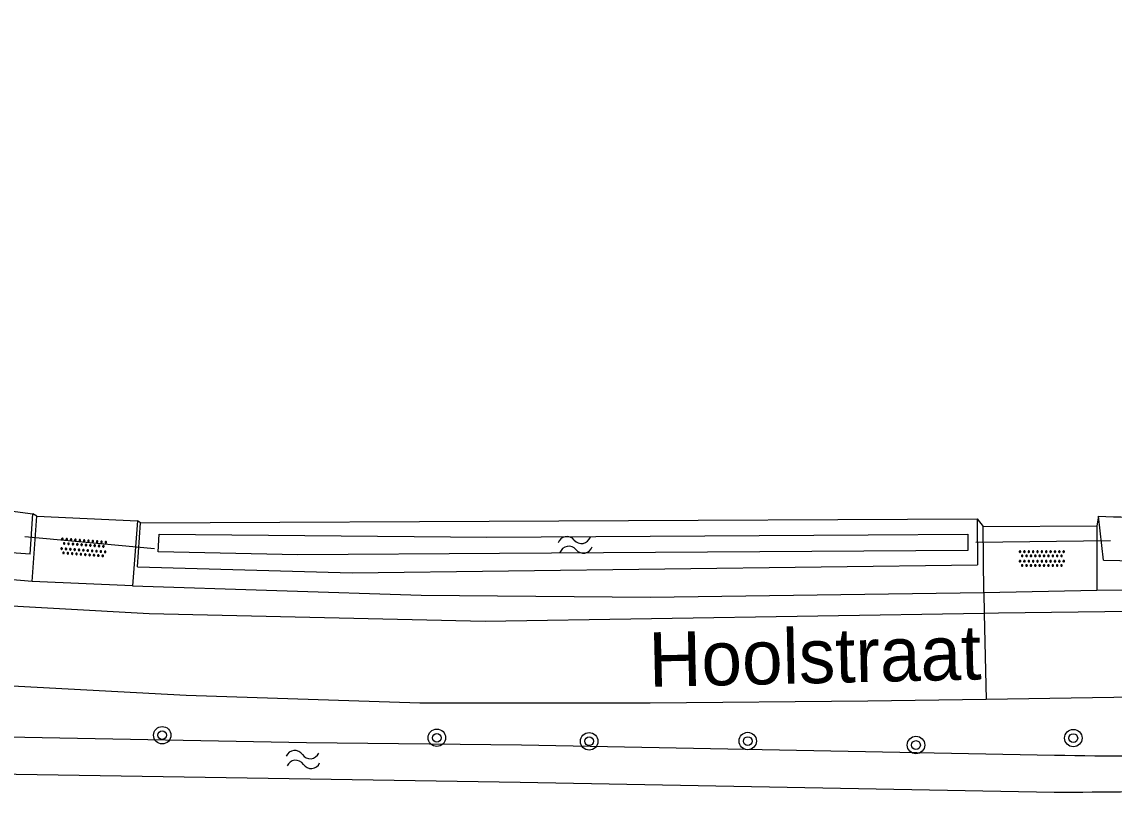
# Model space of a CAD drawing. Extents: x 136000 to 141000, y 400494 to 402006.
# Drawn here: x 138130.6 to 138180.6, y 400789.5 to 400824.8 of the extents above; entities that cross this region are included whole.
import ezdxf

# ---------------------------------------------------------------- set-up
doc = ezdxf.new("R2010")
doc.units = 0
for name, color, linetype in [('gg-anno-openbare ruimte label', 7, 'Continuous'), ('gg-knt-verharding', 7, 'Continuous'), ('gg-knt-verharding nz', 7, 'Continuous'), ('gg-kntw-bovenkant insteek waterloop', 7, 'Continuous'), ('gg-kntw-waterlijn', 7, 'Continuous'), ('gg-kwrk-duiker nz buis', 7, 'Continuous'), ('gt-grn-groengrens', 7, 'Continuous'), ('gt-grn-weggrens', 7, 'Continuous'), ('gt-symb-boom', 7, 'Continuous'), ('gt-symb-overige verharding', 7, 'Continuous'), ('gt-symb-watersymbool', 7, 'Continuous')]:
    doc.layers.add(name, color=color, linetype=linetype)

# ---------------------------------------------------------------- blocks, each defined once
blk = doc.blocks.new('gt0-BOOM')
at = {"layer": 'gt-symb-boom'}
for radius in [0.4, 0.2]:
    blk.add_circle((0, 0), radius, dxfattribs=at)
blk = doc.blocks.new('gt0-WA')
at = {"layer": 'gt-symb-watersymbool'}
for centre, start, end in [((-0.323, 0.022), 28.0725, 151.9275), ((0.427, 0.422), 208.0725, 331.9275), ((-0.323, -0.428), 28.0725, 151.9275), ((0.427, -0.028), 208.0725, 331.9275)]:
    blk.add_arc(centre, 0.425, start, end, dxfattribs=at)
blk = doc.blocks.new('gt0-OVH')
at = {"layer": 'gt-symb-overige verharding'}
for points in [[(-0.972, 0.298), (-0.967, 0.308), (-0.965, 0.319), (-0.966, 0.33), (-0.971, 0.34), (-0.978, 0.348), (-0.988, 0.353), (-0.999, 0.355), (-1.01, 0.354), (-1.02, 0.349), (-1.028, 0.342), (-1.033, 0.332), (-1.035, 0.321), (-1.034, 0.31), (-1.029, 0.3), (-1.022, 0.292), (-1.012, 0.287), (-1.001, 0.285), (-0.99, 0.286), (-0.98, 0.291)], [(-0.872, 0.106), (-0.867, 0.116), (-0.865, 0.126), (-0.866, 0.137), (-0.871, 0.147), (-0.878, 0.156), (-0.888, 0.161), (-0.899, 0.163), (-0.91, 0.162), (-0.92, 0.157), (-0.928, 0.15), (-0.933, 0.14), (-0.935, 0.129), (-0.934, 0.118), (-0.929, 0.108), (-0.922, 0.1), (-0.912, 0.095), (-0.901, 0.092), (-0.89, 0.094), (-0.88, 0.098)], [(-0.772, 0.298), (-0.767, 0.308), (-0.765, 0.319), (-0.766, 0.33), (-0.771, 0.34), (-0.778, 0.348), (-0.788, 0.353), (-0.799, 0.355), (-0.81, 0.354), (-0.82, 0.349), (-0.828, 0.342), (-0.833, 0.332), (-0.835, 0.321), (-0.834, 0.31), (-0.829, 0.3), (-0.822, 0.292), (-0.812, 0.287), (-0.801, 0.285), (-0.79, 0.286), (-0.78, 0.291)], [(-0.672, 0.106), (-0.667, 0.116), (-0.665, 0.126), (-0.666, 0.137), (-0.671, 0.147), (-0.678, 0.156), (-0.688, 0.161), (-0.699, 0.163), (-0.71, 0.162), (-0.72, 0.157), (-0.728, 0.15), (-0.733, 0.14), (-0.735, 0.129), (-0.734, 0.118), (-0.729, 0.108), (-0.722, 0.1), (-0.712, 0.095), (-0.701, 0.092), (-0.69, 0.094), (-0.68, 0.098)], [(-0.572, 0.298), (-0.567, 0.308), (-0.565, 0.319), (-0.566, 0.33), (-0.571, 0.34), (-0.578, 0.348), (-0.588, 0.353), (-0.599, 0.355), (-0.61, 0.354), (-0.62, 0.349), (-0.628, 0.342), (-0.633, 0.332), (-0.635, 0.321), (-0.634, 0.31), (-0.629, 0.3), (-0.622, 0.292), (-0.612, 0.287), (-0.601, 0.285), (-0.59, 0.286), (-0.58, 0.291)], [(-0.472, 0.106), (-0.467, 0.116), (-0.465, 0.126), (-0.466, 0.137), (-0.471, 0.147), (-0.478, 0.156), (-0.488, 0.161), (-0.499, 0.163), (-0.51, 0.162), (-0.52, 0.157), (-0.528, 0.15), (-0.533, 0.14), (-0.535, 0.129), (-0.534, 0.118), (-0.529, 0.108), (-0.522, 0.1), (-0.512, 0.095), (-0.501, 0.092), (-0.49, 0.094), (-0.48, 0.098)], [(-0.372, 0.298), (-0.367, 0.308), (-0.365, 0.319), (-0.366, 0.33), (-0.371, 0.34), (-0.378, 0.348), (-0.388, 0.353), (-0.399, 0.355), (-0.41, 0.354), (-0.42, 0.349), (-0.428, 0.342), (-0.433, 0.332), (-0.435, 0.321), (-0.434, 0.31), (-0.429, 0.3), (-0.422, 0.292), (-0.412, 0.287), (-0.401, 0.285), (-0.39, 0.286), (-0.38, 0.291)], [(-0.272, 0.106), (-0.267, 0.116), (-0.265, 0.126), (-0.266, 0.137), (-0.271, 0.147), (-0.278, 0.156), (-0.288, 0.161), (-0.299, 0.163), (-0.31, 0.162), (-0.32, 0.157), (-0.328, 0.15), (-0.333, 0.14), (-0.335, 0.129), (-0.334, 0.118), (-0.329, 0.108), (-0.322, 0.1), (-0.312, 0.095), (-0.301, 0.092), (-0.29, 0.094), (-0.28, 0.098)], [(-0.172, 0.298), (-0.167, 0.308), (-0.165, 0.319), (-0.166, 0.33), (-0.171, 0.34), (-0.178, 0.348), (-0.188, 0.353), (-0.199, 0.355), (-0.21, 0.354), (-0.22, 0.349), (-0.228, 0.342), (-0.233, 0.332), (-0.235, 0.321), (-0.234, 0.31), (-0.229, 0.3), (-0.222, 0.292), (-0.212, 0.287), (-0.201, 0.285), (-0.19, 0.286), (-0.18, 0.291)], [(-0.072, 0.106), (-0.067, 0.116), (-0.065, 0.126), (-0.066, 0.137), (-0.071, 0.147), (-0.078, 0.156), (-0.088, 0.161), (-0.099, 0.163), (-0.11, 0.162), (-0.12, 0.157), (-0.128, 0.15), (-0.133, 0.14), (-0.135, 0.129), (-0.134, 0.118), (-0.129, 0.108), (-0.122, 0.1), (-0.112, 0.095), (-0.101, 0.092), (-0.09, 0.094), (-0.08, 0.098)], [(0.028, 0.298), (0.033, 0.308), (0.035, 0.319), (0.034, 0.33), (0.029, 0.34), (0.022, 0.348), (0.012, 0.353), (0.001, 0.355), (-0.01, 0.354), (-0.02, 0.349), (-0.028, 0.342), (-0.033, 0.332), (-0.035, 0.321), (-0.034, 0.31), (-0.029, 0.3), (-0.022, 0.292), (-0.012, 0.287), (-0.001, 0.285), (0.01, 0.286), (0.02, 0.291)], [(0.128, 0.106), (0.133, 0.116), (0.135, 0.126), (0.134, 0.137), (0.129, 0.147), (0.122, 0.156), (0.112, 0.161), (0.101, 0.163), (0.09, 0.162), (0.08, 0.157), (0.072, 0.15), (0.067, 0.14), (0.065, 0.129), (0.066, 0.118), (0.071, 0.108), (0.078, 0.1), (0.088, 0.095), (0.099, 0.092), (0.11, 0.094), (0.12, 0.098)], [(0.228, 0.298), (0.233, 0.308), (0.235, 0.319), (0.234, 0.33), (0.229, 0.34), (0.222, 0.348), (0.212, 0.353), (0.201, 0.355), (0.19, 0.354), (0.18, 0.349), (0.172, 0.342), (0.167, 0.332), (0.165, 0.321), (0.166, 0.31), (0.171, 0.3), (0.178, 0.292), (0.188, 0.287), (0.199, 0.285), (0.21, 0.286), (0.22, 0.291)], [(0.328, 0.106), (0.333, 0.116), (0.335, 0.126), (0.334, 0.137), (0.329, 0.147), (0.322, 0.156), (0.312, 0.161), (0.301, 0.163), (0.29, 0.162), (0.28, 0.157), (0.272, 0.15), (0.267, 0.14), (0.265, 0.129), (0.266, 0.118), (0.271, 0.108), (0.278, 0.1), (0.288, 0.095), (0.299, 0.092), (0.31, 0.094), (0.32, 0.098)], [(0.428, 0.298), (0.433, 0.308), (0.435, 0.319), (0.434, 0.33), (0.429, 0.34), (0.422, 0.348), (0.412, 0.353), (0.401, 0.355), (0.39, 0.354), (0.38, 0.349), (0.372, 0.342), (0.367, 0.332), (0.365, 0.321), (0.366, 0.31), (0.371, 0.3), (0.378, 0.292), (0.388, 0.287), (0.399, 0.285), (0.41, 0.286), (0.42, 0.291)], [(0.528, 0.106), (0.533, 0.116), (0.535, 0.126), (0.534, 0.137), (0.529, 0.147), (0.522, 0.156), (0.512, 0.161), (0.501, 0.163), (0.49, 0.162), (0.48, 0.157), (0.472, 0.15), (0.467, 0.14), (0.465, 0.129), (0.466, 0.118), (0.471, 0.108), (0.478, 0.1), (0.488, 0.095), (0.499, 0.092), (0.51, 0.094), (0.52, 0.098)], [(0.628, 0.298), (0.633, 0.308), (0.635, 0.319), (0.634, 0.33), (0.629, 0.34), (0.622, 0.348), (0.612, 0.353), (0.601, 0.355), (0.59, 0.354), (0.58, 0.349), (0.572, 0.342), (0.567, 0.332), (0.565, 0.321), (0.566, 0.31), (0.571, 0.3), (0.578, 0.292), (0.588, 0.287), (0.599, 0.285), (0.61, 0.286), (0.62, 0.291)], [(0.728, 0.106), (0.733, 0.116), (0.735, 0.126), (0.734, 0.137), (0.729, 0.147), (0.722, 0.156), (0.712, 0.161), (0.701, 0.163), (0.69, 0.162), (0.68, 0.157), (0.672, 0.15), (0.667, 0.14), (0.665, 0.129), (0.666, 0.118), (0.671, 0.108), (0.678, 0.1), (0.688, 0.095), (0.699, 0.092), (0.71, 0.094), (0.72, 0.098)], [(0.828, 0.298), (0.833, 0.308), (0.835, 0.319), (0.834, 0.33), (0.829, 0.34), (0.822, 0.348), (0.812, 0.353), (0.801, 0.355), (0.79, 0.354), (0.78, 0.349), (0.772, 0.342), (0.767, 0.332), (0.765, 0.321), (0.766, 0.31), (0.771, 0.3), (0.778, 0.292), (0.788, 0.287), (0.799, 0.285), (0.81, 0.286), (0.82, 0.291)], [(0.928, 0.106), (0.933, 0.116), (0.935, 0.126), (0.934, 0.137), (0.929, 0.147), (0.922, 0.156), (0.912, 0.161), (0.901, 0.163), (0.89, 0.162), (0.88, 0.157), (0.872, 0.15), (0.867, 0.14), (0.865, 0.129), (0.866, 0.118), (0.871, 0.108), (0.878, 0.1), (0.888, 0.095), (0.899, 0.092), (0.91, 0.094), (0.92, 0.098)], [(1.028, 0.298), (1.033, 0.308), (1.035, 0.319), (1.034, 0.33), (1.029, 0.34), (1.022, 0.348), (1.012, 0.353), (1.001, 0.355), (0.99, 0.354), (0.98, 0.349), (0.972, 0.342), (0.967, 0.332), (0.965, 0.321), (0.966, 0.31), (0.971, 0.3), (0.978, 0.292), (0.988, 0.287), (0.999, 0.285), (1.01, 0.286), (1.02, 0.291)], [(-0.972, -0.142), (-0.967, -0.132), (-0.965, -0.121), (-0.966, -0.11), (-0.971, -0.1), (-0.978, -0.092), (-0.988, -0.087), (-0.999, -0.085), (-1.01, -0.086), (-1.02, -0.091), (-1.028, -0.098), (-1.033, -0.108), (-1.035, -0.119), (-1.034, -0.13), (-1.029, -0.14), (-1.022, -0.148), (-1.012, -0.153), (-1.001, -0.155), (-0.99, -0.154), (-0.98, -0.149)], [(-0.872, -0.334), (-0.867, -0.324), (-0.865, -0.314), (-0.866, -0.303), (-0.871, -0.293), (-0.878, -0.284), (-0.888, -0.279), (-0.899, -0.277), (-0.91, -0.278), (-0.92, -0.283), (-0.928, -0.29), (-0.933, -0.3), (-0.935, -0.311), (-0.934, -0.322), (-0.929, -0.332), (-0.922, -0.34), (-0.912, -0.345), (-0.901, -0.348), (-0.89, -0.346), (-0.88, -0.342)], [(-0.772, -0.142), (-0.767, -0.132), (-0.765, -0.121), (-0.766, -0.11), (-0.771, -0.1), (-0.778, -0.092), (-0.788, -0.087), (-0.799, -0.085), (-0.81, -0.086), (-0.82, -0.091), (-0.828, -0.098), (-0.833, -0.108), (-0.835, -0.119), (-0.834, -0.13), (-0.829, -0.14), (-0.822, -0.148), (-0.812, -0.153), (-0.801, -0.155), (-0.79, -0.154), (-0.78, -0.149)], [(-0.672, -0.334), (-0.667, -0.324), (-0.665, -0.314), (-0.666, -0.303), (-0.671, -0.293), (-0.678, -0.284), (-0.688, -0.279), (-0.699, -0.277), (-0.71, -0.278), (-0.72, -0.283), (-0.728, -0.29), (-0.733, -0.3), (-0.735, -0.311), (-0.734, -0.322), (-0.729, -0.332), (-0.722, -0.34), (-0.712, -0.345), (-0.701, -0.348), (-0.69, -0.346), (-0.68, -0.342)], [(-0.572, -0.142), (-0.567, -0.132), (-0.565, -0.121), (-0.566, -0.11), (-0.571, -0.1), (-0.578, -0.092), (-0.588, -0.087), (-0.599, -0.085), (-0.61, -0.086), (-0.62, -0.091), (-0.628, -0.098), (-0.633, -0.108), (-0.635, -0.119), (-0.634, -0.13), (-0.629, -0.14), (-0.622, -0.148), (-0.612, -0.153), (-0.601, -0.155), (-0.59, -0.154), (-0.58, -0.149)], [(-0.472, -0.334), (-0.467, -0.324), (-0.465, -0.314), (-0.466, -0.303), (-0.471, -0.293), (-0.478, -0.284), (-0.488, -0.279), (-0.499, -0.277), (-0.51, -0.278), (-0.52, -0.283), (-0.528, -0.29), (-0.533, -0.3), (-0.535, -0.311), (-0.534, -0.322), (-0.529, -0.332), (-0.522, -0.34), (-0.512, -0.345), (-0.501, -0.348), (-0.49, -0.346), (-0.48, -0.342)], [(-0.372, -0.142), (-0.367, -0.132), (-0.365, -0.121), (-0.366, -0.11), (-0.371, -0.1), (-0.378, -0.092), (-0.388, -0.087), (-0.399, -0.085), (-0.41, -0.086), (-0.42, -0.091), (-0.428, -0.098), (-0.433, -0.108), (-0.435, -0.119), (-0.434, -0.13), (-0.429, -0.14), (-0.422, -0.148), (-0.412, -0.153), (-0.401, -0.155), (-0.39, -0.154), (-0.38, -0.149)], [(-0.272, -0.334), (-0.267, -0.324), (-0.265, -0.314), (-0.266, -0.303), (-0.271, -0.293), (-0.278, -0.284), (-0.288, -0.279), (-0.299, -0.277), (-0.31, -0.278), (-0.32, -0.283), (-0.328, -0.29), (-0.333, -0.3), (-0.335, -0.311), (-0.334, -0.322), (-0.329, -0.332), (-0.322, -0.34), (-0.312, -0.345), (-0.301, -0.348), (-0.29, -0.346), (-0.28, -0.342)], [(-0.172, -0.142), (-0.167, -0.132), (-0.165, -0.121), (-0.166, -0.11), (-0.171, -0.1), (-0.178, -0.092), (-0.188, -0.087), (-0.199, -0.085), (-0.21, -0.086), (-0.22, -0.091), (-0.228, -0.098), (-0.233, -0.108), (-0.235, -0.119), (-0.234, -0.13), (-0.229, -0.14), (-0.222, -0.148), (-0.212, -0.153), (-0.201, -0.155), (-0.19, -0.154), (-0.18, -0.149)], [(-0.072, -0.334), (-0.067, -0.324), (-0.065, -0.314), (-0.066, -0.303), (-0.071, -0.293), (-0.078, -0.284), (-0.088, -0.279), (-0.099, -0.277), (-0.11, -0.278), (-0.12, -0.283), (-0.128, -0.29), (-0.133, -0.3), (-0.135, -0.311), (-0.134, -0.322), (-0.129, -0.332), (-0.122, -0.34), (-0.112, -0.345), (-0.101, -0.348), (-0.09, -0.346), (-0.08, -0.342)], [(0.028, -0.142), (0.033, -0.132), (0.035, -0.121), (0.034, -0.11), (0.029, -0.1), (0.022, -0.092), (0.012, -0.087), (0.001, -0.085), (-0.01, -0.086), (-0.02, -0.091), (-0.028, -0.098), (-0.033, -0.108), (-0.035, -0.119), (-0.034, -0.13), (-0.029, -0.14), (-0.022, -0.148), (-0.012, -0.153), (-0.001, -0.155), (0.01, -0.154), (0.02, -0.149)], [(0.128, -0.334), (0.133, -0.324), (0.135, -0.314), (0.134, -0.303), (0.129, -0.293), (0.122, -0.284), (0.112, -0.279), (0.101, -0.277), (0.09, -0.278), (0.08, -0.283), (0.072, -0.29), (0.067, -0.3), (0.065, -0.311), (0.066, -0.322), (0.071, -0.332), (0.078, -0.34), (0.088, -0.345), (0.099, -0.348), (0.11, -0.346), (0.12, -0.342)], [(0.228, -0.142), (0.233, -0.132), (0.235, -0.121), (0.234, -0.11), (0.229, -0.1), (0.222, -0.092), (0.212, -0.087), (0.201, -0.085), (0.19, -0.086), (0.18, -0.091), (0.172, -0.098), (0.167, -0.108), (0.165, -0.119), (0.166, -0.13), (0.171, -0.14), (0.178, -0.148), (0.188, -0.153), (0.199, -0.155), (0.21, -0.154), (0.22, -0.149)], [(0.328, -0.334), (0.333, -0.324), (0.335, -0.314), (0.334, -0.303), (0.329, -0.293), (0.322, -0.284), (0.312, -0.279), (0.301, -0.277), (0.29, -0.278), (0.28, -0.283), (0.272, -0.29), (0.267, -0.3), (0.265, -0.311), (0.266, -0.322), (0.271, -0.332), (0.278, -0.34), (0.288, -0.345), (0.299, -0.348), (0.31, -0.346), (0.32, -0.342)], [(0.428, -0.142), (0.433, -0.132), (0.435, -0.121), (0.434, -0.11), (0.429, -0.1), (0.422, -0.092), (0.412, -0.087), (0.401, -0.085), (0.39, -0.086), (0.38, -0.091), (0.372, -0.098), (0.367, -0.108), (0.365, -0.119), (0.366, -0.13), (0.371, -0.14), (0.378, -0.148), (0.388, -0.153), (0.399, -0.155), (0.41, -0.154), (0.42, -0.149)], [(0.528, -0.334), (0.533, -0.324), (0.535, -0.314), (0.534, -0.303), (0.529, -0.293), (0.522, -0.284), (0.512, -0.279), (0.501, -0.277), (0.49, -0.278), (0.48, -0.283), (0.472, -0.29), (0.467, -0.3), (0.465, -0.311), (0.466, -0.322), (0.471, -0.332), (0.478, -0.34), (0.488, -0.345), (0.499, -0.348), (0.51, -0.346), (0.52, -0.342)], [(0.628, -0.142), (0.633, -0.132), (0.635, -0.121), (0.634, -0.11), (0.629, -0.1), (0.622, -0.092), (0.612, -0.087), (0.601, -0.085), (0.59, -0.086), (0.58, -0.091), (0.572, -0.098), (0.567, -0.108), (0.565, -0.119), (0.566, -0.13), (0.571, -0.14), (0.578, -0.148), (0.588, -0.153), (0.599, -0.155), (0.61, -0.154), (0.62, -0.149)], [(0.728, -0.334), (0.733, -0.324), (0.735, -0.314), (0.734, -0.303), (0.729, -0.293), (0.722, -0.284), (0.712, -0.279), (0.701, -0.277), (0.69, -0.278), (0.68, -0.283), (0.672, -0.29), (0.667, -0.3), (0.665, -0.311), (0.666, -0.322), (0.671, -0.332), (0.678, -0.34), (0.688, -0.345), (0.699, -0.348), (0.71, -0.346), (0.72, -0.342)], [(0.828, -0.142), (0.833, -0.132), (0.835, -0.121), (0.834, -0.11), (0.829, -0.1), (0.822, -0.092), (0.812, -0.087), (0.801, -0.085), (0.79, -0.086), (0.78, -0.091), (0.772, -0.098), (0.767, -0.108), (0.765, -0.119), (0.766, -0.13), (0.771, -0.14), (0.778, -0.148), (0.788, -0.153), (0.799, -0.155), (0.81, -0.154), (0.82, -0.149)], [(0.928, -0.334), (0.933, -0.324), (0.935, -0.314), (0.934, -0.303), (0.929, -0.293), (0.922, -0.284), (0.912, -0.279), (0.901, -0.277), (0.89, -0.278), (0.88, -0.283), (0.872, -0.29), (0.867, -0.3), (0.865, -0.311), (0.866, -0.322), (0.871, -0.332), (0.878, -0.34), (0.888, -0.345), (0.899, -0.348), (0.91, -0.346), (0.92, -0.342)], [(1.028, -0.142), (1.033, -0.132), (1.035, -0.121), (1.034, -0.11), (1.029, -0.1), (1.022, -0.092), (1.012, -0.087), (1.001, -0.085), (0.99, -0.086), (0.98, -0.091), (0.972, -0.098), (0.967, -0.108), (0.965, -0.119), (0.966, -0.13), (0.971, -0.14), (0.978, -0.148), (0.988, -0.153), (0.999, -0.155), (1.01, -0.154), (1.02, -0.149)]]:
    blk.add_lwpolyline(points, close=True, dxfattribs=at)

msp = doc.modelspace()

# ---------------------------------------------------------------- linework, layer by layer
at = {"layer": 'gg-knt-verharding'}
for p, q in [((138131.08, 400799.184), (138131.289, 400802.18)), ((138131.289, 400802.18), (138135.9, 400801.967)), ((138135.9, 400801.967), (138135.682, 400798.981)), ((138174.636, 400801.713), (138179.841, 400801.73)), ((138174.67, 400798.681), (138174.636, 400801.713)), ((138179.841, 400801.73), (138179.846, 400798.788)), ((138135.682, 400798.981), (138131.08, 400799.184)), ((138174.67, 400798.681), (138179.846, 400798.788))]:
    msp.add_line(p, q, dxfattribs=at)
for points in [[(138131.08, 400799.184), (138125.533, 400799.66), (138116.669, 400801.27), (138107.503, 400803.583), (138087.491, 400808.865)], [(138179.846, 400798.788), (138187.398, 400798.869), (138197.334, 400799.087), (138207.029, 400799.638), (138217.56, 400800.828), (138227.412, 400802.515), (138234.814, 400804.057)], [(138135.682, 400798.981), (138148.903, 400798.558), (138159.404, 400798.472), (138174.67, 400798.681)], [(138174.771, 400793.785), (138169.361, 400793.7), (138159.388, 400793.608), (138148.84, 400793.618), (138138.131, 400793.97), (138128.158, 400794.496)], [(138192.526, 400794.094), (138187.44, 400793.983), (138174.771, 400793.785)]]:
    msp.add_lwpolyline(points, dxfattribs=at)
at = {"layer": 'gg-knt-verharding nz'}
for points in [[(138174.69, 400797.724), (138151.824, 400797.351), (138136.433, 400797.7), (138128.477, 400798.154), (138121.183, 400799.167), (138102.931, 400803.74), (138083.947, 400808.662), (138068.801, 400812.607), (138057.633, 400815.225), (138018.966, 400823.812), (138014.22, 400824.825)], [(138297.427, 400822.39), (138296.023, 400821.683), (138290.195, 400819.554), (138280.772, 400816.516), (138270.408, 400813.305), (138249.259, 400806.882), (138241.023, 400804.508), (138232.718, 400802.553), (138222.143, 400800.563), (138214.815, 400799.446), (138205.951, 400798.503), (138192.375, 400797.945), (138175.345, 400797.735), (138174.69, 400797.724)]]:
    msp.add_lwpolyline(points, dxfattribs=at)
at = {"layer": 'gg-kntw-bovenkant insteek waterloop'}
for p, q in [((138125.497, 400803.003), (138131.107, 400802.287)), ((138130.981, 400800.436), (138131.107, 400802.287)), ((138135.906, 400799.851), (138136.044, 400801.873)), ((138136.044, 400801.873), (138174.372, 400802.064)), ((138174.372, 400802.064), (138174.382, 400799.95)), ((138180.156, 400800.164), (138179.918, 400802.172)), ((138130.981, 400800.436), (138125.125, 400800.835))]:
    msp.add_line(p, q, dxfattribs=at)
for points in [[(138135.906, 400799.851), (138145.739, 400799.59), (138174.382, 400799.95)], [(138128.405, 400790.395), (138128.307, 400792.097), (138143.643, 400791.808), (138153.497, 400791.699), (138177.916, 400791.236)], [(138128.405, 400790.395), (138153.434, 400790), (138177.898, 400789.536)]]:
    msp.add_lwpolyline(points, dxfattribs=at)
for centre, radius, start, end in [((138187.722, 401049.606), 249.557, 268.26265, 279.11269), ((138187.747, 401051.321), 249.272, 268.20029, 270.72508), ((138183.359, 401080.518), 289.333, 268.9221, 271.82772), ((138175.943, 401320.509), 530.976, 270.211, 271.7105)]:
    msp.add_arc(centre, radius, start, end, dxfattribs=at)
at = {"layer": 'gg-kntw-waterlijn'}
msp.add_lwpolyline([(138136.891, 400801.354), (138151.904, 400801.224), (138169.371, 400801.33), (138173.933, 400801.357), (138173.938, 400800.599), (138152.49, 400800.469), (138143.247, 400800.414), (138136.854, 400800.546), (138136.891, 400801.354)], dxfattribs=at)
at = {"layer": 'gg-kwrk-duiker nz buis'}
for p, q in [((138136.685, 400800.681), (138130.746, 400801.228)), ((138180.469, 400801.054), (138174.304, 400800.966))]:
    msp.add_line(p, q, dxfattribs=at)
at = {"layer": 'gt-grn-groengrens'}
for p, q in [((138131.289, 400802.18), (138131.107, 400802.287)), ((138136.044, 400801.873), (138135.9, 400801.967)), ((138174.372, 400802.064), (138174.636, 400801.713)), ((138179.918, 400802.172), (138179.841, 400801.73))]:
    msp.add_line(p, q, dxfattribs=at)
at = {"layer": 'gt-grn-weggrens'}
for p, q in [((138174.67, 400798.681), (138174.69, 400797.724)), ((138174.69, 400797.724), (138174.771, 400793.785))]:
    msp.add_line(p, q, dxfattribs=at)

# ---------------------------------------------------------------- block references
at = {"layer": 'gt-symb-boom'}
for p in [(138137.037, 400792.144), (138149.616, 400792.028), (138178.77, 400792.013), (138156.593, 400791.866), (138163.857, 400791.877), (138171.563, 400791.695)]:
    msp.add_blockref('gt0-BOOM', p, dxfattribs=at)
at = {"layer": 'gt-symb-overige verharding', "rotation": -4.302011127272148}
msp.add_blockref('gt0-OVH', (138133.435, 400800.738), dxfattribs=at)
at = {"layer": 'gt-symb-overige verharding'}
msp.add_blockref('gt0-OVH', (138177.33, 400800.233), dxfattribs=at)
at = {"layer": 'gt-symb-watersymbool'}
for p, rotation in [((138155.9, 400800.859), 10.48938981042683), ((138143.428, 400791.029), 5.5109769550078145)]:
    msp.add_blockref('gt0-WA', p, dxfattribs=dict(at, rotation=rotation))

# ---------------------------------------------------------------- texts
at = {"layer": 'gg-anno-openbare ruimte label'}
msp.add_text('Hoolstraat', height=2.5, rotation=1.3, dxfattribs=at).set_placement((138159.345, 400794.355))

doc.saveas('drawing.dxf')
